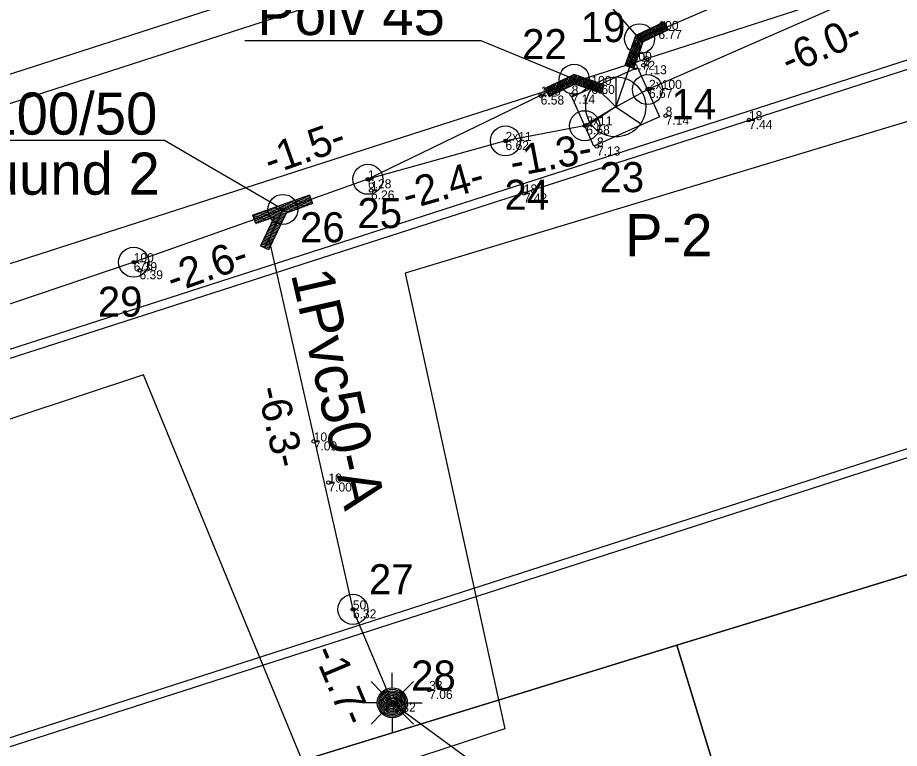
# Model space of a CAD drawing. Extents: x 546339 to 546593, y 6597108 to 6597251.
# Drawn here: x 546468.19 to 546482.86, y 6597179 to 6597191.16 of the extents above; entities that cross this region are included whole.
import ezdxf

# ---------------------------------------------------------------- set-up
doc = ezdxf.new("R2010")
doc.units = 0
for name, color, linetype in [('JOONSIDE', 7, 'Continuous'), ('KAEVUNR_SIKAEV', 7, 'Continuous'), ('KOORDPUNKT', 7, 'Continuous'), ('MOOTKORG-EH2000', 7, 'Continuous'), ('MOOTMPUNKT', 7, 'Continuous'), ('MOOTNR', 7, 'Continuous'), ('MOOTPIIR', 7, 'Continuous'), ('PIIR', 7, 'Continuous'), ('SIKAEV', 7, 'Continuous'), ('SITRASS', 7, 'Continuous'), ('TEE', 7, 'Continuous')]:
    doc.layers.add(name, color=color, linetype=linetype)

msp = doc.modelspace()

# ---------------------------------------------------------------- linework, layer by layer
at = {"layer": 'KOORDPUNKT'}
for centre, radius in [((546478.539, 6597190.81), 0.25), ((546478.539, 6597190.81), 0.025), ((546478.539, 6597190.81), 0.0221), ((546478.539, 6597190.81), 0.0191), ((546478.539, 6597190.81), 0.0161), ((546478.539, 6597190.81), 0.0132), ((546478.539, 6597190.81), 0.0102), ((546478.539, 6597190.81), 0.00726), ((546478.539, 6597190.81), 0.0043), ((546477.452, 6597190.136), 0.25), ((546477.452, 6597190.136), 0.025), ((546477.452, 6597190.136), 0.0221), ((546478.67, 6597189.965), 0.25), ((546477.452, 6597190.136), 0.0191), ((546477.452, 6597190.136), 0.0161), ((546477.452, 6597190.136), 0.0132), ((546477.452, 6597190.136), 0.0102), ((546477.452, 6597190.136), 0.00726), ((546477.452, 6597190.136), 0.0043), ((546478.67, 6597189.965), 0.025), ((546478.67, 6597189.965), 0.0221), ((546478.67, 6597189.965), 0.0191), ((546478.67, 6597189.965), 0.0161), ((546478.67, 6597189.965), 0.0132), ((546478.67, 6597189.965), 0.0102), ((546478.67, 6597189.965), 0.00726), ((546478.67, 6597189.965), 0.0043), ((546477.625, 6597189.363), 0.25), ((546476.307, 6597189.11), 0.25), ((546477.625, 6597189.363), 0.025), ((546477.625, 6597189.363), 0.0221), ((546477.625, 6597189.363), 0.0191), ((546477.625, 6597189.363), 0.0161), ((546477.625, 6597189.363), 0.0132), ((546477.625, 6597189.363), 0.0102), ((546477.625, 6597189.363), 0.00726), ((546477.625, 6597189.363), 0.0043), ((546476.307, 6597189.11), 0.025), ((546476.307, 6597189.11), 0.0221), ((546476.307, 6597189.11), 0.0191), ((546476.307, 6597189.11), 0.0161), ((546476.307, 6597189.11), 0.0132), ((546476.307, 6597189.11), 0.0102), ((546476.307, 6597189.11), 0.00726), ((546476.307, 6597189.11), 0.0043), ((546474.017, 6597188.471), 0.25), ((546474.017, 6597188.471), 0.025), ((546474.017, 6597188.471), 0.0221), ((546474.017, 6597188.471), 0.0191), ((546474.017, 6597188.471), 0.0161), ((546474.017, 6597188.471), 0.0132), ((546474.017, 6597188.471), 0.0102), ((546474.017, 6597188.471), 0.00726), ((546474.017, 6597188.471), 0.0043), ((546472.601, 6597187.97), 0.25), ((546472.601, 6597187.97), 0.025), ((546472.601, 6597187.97), 0.0221), ((546472.601, 6597187.97), 0.0191), ((546472.601, 6597187.97), 0.0161), ((546472.601, 6597187.97), 0.0132), ((546472.601, 6597187.97), 0.0102), ((546472.601, 6597187.97), 0.00726), ((546472.601, 6597187.97), 0.0043), ((546470.118, 6597187.092), 0.25), ((546470.118, 6597187.092), 0.025), ((546470.118, 6597187.092), 0.0221), ((546470.118, 6597187.092), 0.0191), ((546470.118, 6597187.092), 0.0161), ((546470.118, 6597187.092), 0.0132), ((546470.118, 6597187.092), 0.0102), ((546470.118, 6597187.092), 0.00726), ((546470.118, 6597187.092), 0.0043), ((546473.767, 6597181.315), 0.25), ((546473.767, 6597181.315), 0.025), ((546473.767, 6597181.315), 0.0221), ((546473.767, 6597181.315), 0.0191), ((546473.767, 6597181.315), 0.0161), ((546473.767, 6597181.315), 0.0132), ((546473.767, 6597181.315), 0.0102), ((546473.767, 6597181.315), 0.00726), ((546473.767, 6597181.315), 0.0043), ((546474.423, 6597179.76), 0.25), ((546474.423, 6597179.76), 0.025), ((546474.423, 6597179.76), 0.0221), ((546474.423, 6597179.76), 0.0191), ((546474.423, 6597179.76), 0.0161), ((546474.423, 6597179.76), 0.0132), ((546474.423, 6597179.76), 0.0102), ((546474.423, 6597179.76), 0.00726), ((546474.423, 6597179.76), 0.0043)]:
    msp.add_circle(centre, radius, dxfattribs=at)
at = {"layer": 'MOOTMPUNKT'}
for centre in [(546478.853, 6597190.956), (546478.407, 6597190.443), (546478.602, 6597190.369), (546477.737, 6597190.041), (546476.893, 6597189.865), (546477.409, 6597189.881), (546478.696, 6597189.976), (546478.973, 6597189.528), (546480.36, 6597189.456), (546477.653, 6597189.368), (546476.307, 6597189.11), (546477.829, 6597189.017), (546474.017, 6597188.471), (546474.068, 6597188.286), (546476.612, 6597188.235), (546470.118, 6597187.092), (546470.215, 6597186.957), (546473.115, 6597184.109), (546473.36, 6597183.425), (546473.767, 6597181.315), (546475.037, 6597179.974), (546474.423, 6597179.76)]:
    msp.add_circle(centre, 0.03, dxfattribs=at)
at = {"layer": 'MOOTPIIR'}
for points in [[(546431.038, 6597182.742), (546435.363, 6597179.169), (546476.861, 6597192.584), (546477.551, 6597196.157), (546480.466, 6597197.411), (546483.506, 6597194.527), (546510.21, 6597203.146)], [(546510.398, 6597198.602), (546490.433, 6597192.051), (546491.122, 6597184.372), (546487.988, 6597183.494), (546485.449, 6597190.17), (546474.636, 6597186.911), (546476.297, 6597179.326), (546473.131, 6597178.291), (546470.279, 6597185.218), (546447.869, 6597177.79), (546448.872, 6597171.02), (546446.584, 6597170.142), (546443.888, 6597176.348), (546374.62, 6597155.63)]]:
    msp.add_lwpolyline(points, dxfattribs=at)
at = {"layer": 'PIIR'}
for points in [[(546339.379, 6597150.424), (546339.82, 6597150.4), (546343.3, 6597148.09), (546350.66, 6597143.2), (546387.61, 6597151.42), (546402.5, 6597155.95), (546434.27, 6597166.43), (546452.55, 6597172.32), (546467.66, 6597177.18), (546479.16, 6597180.72), (546505.65, 6597188.82)], [(546512.531, 6597166.376), (546505.65, 6597188.82), (546479.16, 6597180.72), (546486.042, 6597158.239)], [(546486.042, 6597158.239), (546479.16, 6597180.72), (546467.66, 6597177.18), (546452.55, 6597172.32), (546459.381, 6597150.05)]]:
    msp.add_lwpolyline(points, dxfattribs=at)
at = {"layer": 'SIKAEV'}
for p, q in [((546478.142, 6597190.176), (546478.142, 6597189.676)), ((546478.142, 6597189.676), (546477.727, 6597189.401)), ((546478.142, 6597189.676), (546478.557, 6597189.401))]:
    msp.add_line(p, q, dxfattribs=at)
msp.add_lwpolyline([(546477.411, 6597189.842), (546478.506, 6597190.332), (546478.873, 6597189.51), (546477.778, 6597189.02)], close=True, dxfattribs=at)
msp.add_circle((546478.142, 6597189.676), 0.5, dxfattribs=at)
at = {"layer": 'SITRASS'}
for p, q in [((546478.957, 6597191.094), (546478.478, 6597190.864)), ((546478.904, 6597190.902), (546478.847, 6597191.042)), ((546478.926, 6597190.913), (546478.869, 6597191.052)), ((546478.949, 6597190.924), (546478.892, 6597191.063)), ((546478.971, 6597190.935), (546478.914, 6597191.074)), ((546478.994, 6597190.946), (546478.937, 6597191.085)), ((546479.022, 6597190.959), (546478.957, 6597191.094)), ((546479.016, 6597190.957), (546478.98, 6597191.046)), ((546478.989, 6597191.027), (546478.539, 6597190.81)), ((546478.61, 6597190.761), (546478.553, 6597190.9)), ((546478.633, 6597190.772), (546478.576, 6597190.911)), ((546478.655, 6597190.783), (546478.598, 6597190.922)), ((546479.022, 6597190.959), (546478.599, 6597190.756)), ((546478.678, 6597190.794), (546478.621, 6597190.933)), ((546478.7, 6597190.805), (546478.644, 6597190.944)), ((546478.723, 6597190.816), (546478.666, 6597190.955)), ((546478.746, 6597190.827), (546478.689, 6597190.966)), ((546478.768, 6597190.837), (546478.711, 6597190.976)), ((546478.791, 6597190.848), (546478.734, 6597190.987)), ((546478.813, 6597190.859), (546478.756, 6597190.998)), ((546478.836, 6597190.87), (546478.779, 6597191.009)), ((546478.858, 6597190.881), (546478.802, 6597191.02)), ((546478.881, 6597190.892), (546478.824, 6597191.031)), ((546478.302, 6597190.363), (546478.478, 6597190.864)), ((546478.373, 6597190.338), (546478.539, 6597190.81)), ((546478.444, 6597190.314), (546478.599, 6597190.756)), ((546478.53, 6597190.56), (546478.445, 6597190.77)), ((546478.543, 6597190.596), (546478.457, 6597190.805)), ((546478.555, 6597190.632), (546478.47, 6597190.841)), ((546478.568, 6597190.667), (546478.486, 6597190.868)), ((546478.58, 6597190.703), (546478.508, 6597190.879)), ((546478.593, 6597190.738), (546478.531, 6597190.89)), ((546478.481, 6597190.418), (546478.395, 6597190.627)), ((546478.493, 6597190.454), (546478.407, 6597190.663)), ((546478.506, 6597190.489), (546478.42, 6597190.698)), ((546478.518, 6597190.525), (546478.432, 6597190.734)), ((546478.411, 6597190.325), (546478.345, 6597190.485)), ((546478.442, 6597190.314), (546478.358, 6597190.521)), ((546478.456, 6597190.347), (546478.37, 6597190.556)), ((546478.468, 6597190.383), (546478.382, 6597190.592)), ((546478.444, 6597190.314), (546478.302, 6597190.363)), ((546478.316, 6597190.358), (546478.308, 6597190.379)), ((546478.348, 6597190.347), (546478.32, 6597190.414)), ((546478.379, 6597190.336), (546478.333, 6597190.45)), ((546476.969, 6597189.986), (546477.447, 6597190.217)), ((546477.27, 6597189.965), (546477.357, 6597190.174)), ((546477.304, 6597189.981), (546477.39, 6597190.19)), ((546477.338, 6597189.998), (546477.424, 6597190.206)), ((546477.372, 6597190.014), (546477.455, 6597190.215)), ((546477.406, 6597190.031), (546477.478, 6597190.206)), ((546477.439, 6597190.047), (546477.502, 6597190.198)), ((546477.949, 6597190.043), (546477.447, 6597190.217)), ((546477.468, 6597190.051), (546477.526, 6597190.19)), ((546477.492, 6597190.043), (546477.549, 6597190.182)), ((546477.516, 6597190.035), (546477.573, 6597190.174)), ((546477.539, 6597190.027), (546477.597, 6597190.165)), ((546477.002, 6597189.918), (546477.452, 6597190.136)), ((546477.005, 6597189.912), (546477.052, 6597190.026)), ((546477.019, 6597189.882), (546477.086, 6597190.042)), ((546477.034, 6597189.852), (546477.119, 6597190.059)), ((546477.035, 6597189.851), (546477.456, 6597190.055)), ((546477.067, 6597189.866), (546477.153, 6597190.075)), ((546477.101, 6597189.883), (546477.187, 6597190.091)), ((546477.134, 6597189.899), (546477.221, 6597190.108)), ((546477.168, 6597189.916), (546477.255, 6597190.124)), ((546477.202, 6597189.932), (546477.289, 6597190.141)), ((546477.236, 6597189.948), (546477.323, 6597190.157)), ((546477.924, 6597189.972), (546477.452, 6597190.136)), ((546477.9, 6597189.902), (546477.456, 6597190.055)), ((546477.563, 6597190.018), (546477.62, 6597190.157)), ((546477.587, 6597190.01), (546477.644, 6597190.149)), ((546477.61, 6597190.002), (546477.668, 6597190.141)), ((546477.634, 6597189.994), (546477.691, 6597190.133)), ((546477.657, 6597189.986), (546477.715, 6597190.124)), ((546477.681, 6597189.977), (546477.739, 6597190.116)), ((546477.705, 6597189.969), (546477.762, 6597190.108)), ((546477.728, 6597189.961), (546477.786, 6597190.1)), ((546477.752, 6597189.953), (546477.81, 6597190.092)), ((546477.776, 6597189.945), (546477.833, 6597190.083)), ((546477.799, 6597189.936), (546477.857, 6597190.075)), ((546477.823, 6597189.928), (546477.881, 6597190.067)), ((546477.847, 6597189.92), (546477.904, 6597190.059)), ((546477.87, 6597189.912), (546477.928, 6597190.051)), ((546477.9, 6597189.902), (546477.949, 6597190.043)), ((546477.035, 6597189.851), (546476.969, 6597189.986)), ((546476.975, 6597189.973), (546476.984, 6597189.993)), ((546476.99, 6597189.943), (546477.018, 6597190.009)), ((546477.894, 6597189.904), (546477.931, 6597189.993)), ((546473.047, 6597188.208), (546472.104, 6597187.874)), ((546473.072, 6597188.137), (546472.129, 6597187.803)), ((546472.753, 6597188.103), (546472.997, 6597188.031)), ((546472.793, 6597188.118), (546473.036, 6597188.045)), ((546472.833, 6597188.132), (546473.076, 6597188.059)), ((546472.873, 6597188.146), (546473.092, 6597188.08)), ((546472.913, 6597188.16), (546473.082, 6597188.109)), ((546472.953, 6597188.174), (546473.071, 6597188.139)), ((546472.993, 6597188.188), (546473.061, 6597188.168)), ((546473.033, 6597188.202), (546473.051, 6597188.197)), ((546473.047, 6597188.208), (546473.097, 6597188.066)), ((546472.601, 6597187.97), (546472.296, 6597187.332)), ((546472.353, 6597187.962), (546472.639, 6597187.876)), ((546472.393, 6597187.976), (546472.65, 6597187.899)), ((546472.433, 6597187.99), (546472.677, 6597187.917)), ((546472.473, 6597188.004), (546472.717, 6597187.932)), ((546472.513, 6597188.019), (546472.757, 6597187.946)), ((546472.553, 6597188.033), (546472.797, 6597187.96)), ((546472.593, 6597188.047), (546472.837, 6597187.974)), ((546472.633, 6597188.061), (546472.877, 6597187.988)), ((546473.097, 6597188.066), (546472.655, 6597187.91)), ((546472.673, 6597188.075), (546472.917, 6597188.002)), ((546472.713, 6597188.089), (546472.957, 6597188.016)), ((546472.154, 6597187.733), (546472.104, 6597187.874)), ((546472.112, 6597187.851), (546472.317, 6597187.79)), ((546472.113, 6597187.877), (546472.357, 6597187.804)), ((546472.123, 6597187.822), (546472.277, 6597187.776)), ((546472.153, 6597187.891), (546472.397, 6597187.818)), ((546472.455, 6597187.839), (546472.154, 6597187.733)), ((546472.193, 6597187.905), (546472.437, 6597187.833)), ((546472.455, 6597187.839), (546472.228, 6597187.364)), ((546472.233, 6597187.92), (546472.606, 6597187.808)), ((546472.273, 6597187.934), (546472.617, 6597187.831)), ((546472.313, 6597187.948), (546472.628, 6597187.854)), ((546472.655, 6597187.91), (546472.364, 6597187.3)), ((546472.45, 6597187.829), (546472.596, 6597187.785)), ((546472.133, 6597187.793), (546472.237, 6597187.762)), ((546472.143, 6597187.764), (546472.197, 6597187.748)), ((546472.154, 6597187.735), (546472.157, 6597187.734)), ((546472.374, 6597187.669), (546472.519, 6597187.625)), ((546472.385, 6597187.692), (546472.53, 6597187.648)), ((546472.396, 6597187.714), (546472.541, 6597187.671)), ((546472.406, 6597187.737), (546472.552, 6597187.694)), ((546472.417, 6597187.76), (546472.563, 6597187.717)), ((546472.428, 6597187.783), (546472.574, 6597187.739)), ((546472.439, 6597187.806), (546472.585, 6597187.762)), ((546472.308, 6597187.532), (546472.454, 6597187.488)), ((546472.319, 6597187.555), (546472.465, 6597187.511)), ((546472.33, 6597187.577), (546472.476, 6597187.534)), ((546472.341, 6597187.6), (546472.486, 6597187.557)), ((546472.352, 6597187.623), (546472.497, 6597187.58)), ((546472.363, 6597187.646), (546472.508, 6597187.602)), ((546472.232, 6597187.372), (546472.377, 6597187.328)), ((546472.243, 6597187.395), (546472.388, 6597187.351)), ((546472.254, 6597187.418), (546472.399, 6597187.374)), ((546472.265, 6597187.44), (546472.41, 6597187.397)), ((546472.276, 6597187.463), (546472.421, 6597187.42)), ((546472.287, 6597187.486), (546472.432, 6597187.443)), ((546472.297, 6597187.509), (546472.443, 6597187.465)), ((546472.364, 6597187.3), (546472.228, 6597187.364)), ((546472.326, 6597187.318), (546472.367, 6597187.306)), ((546474.423, 6597180.01), (546474.423, 6597180.26)), ((546474.246, 6597179.937), (546474.069, 6597180.114)), ((546474.6, 6597179.937), (546474.777, 6597180.114)), ((546474.173, 6597179.76), (546473.923, 6597179.76)), ((546474.673, 6597179.76), (546474.923, 6597179.76)), ((546474.246, 6597179.583), (546474.069, 6597179.406)), ((546474.423, 6597179.51), (546474.423, 6597179.26)), ((546474.6, 6597179.583), (546474.777, 6597179.406))]:
    msp.add_line(p, q, dxfattribs=at)
for points in [[(546478.539, 6597190.81), (546476.485, 6597193.15), (546472.55, 6597193.15)], [(546478.142, 6597189.676), (546478.67, 6597189.965), (546484.189, 6597192.382)], [(546480.094, 6597191.481), (546478.539, 6597190.81), (546478.346, 6597190.26), (546478.142, 6597189.676)], [(546477.452, 6597190.136), (546475.905, 6597190.773), (546471.971, 6597190.773)], [(546478.142, 6597189.676), (546477.799, 6597190.016), (546477.452, 6597190.136), (546474.017, 6597188.471)], [(546478.142, 6597189.676), (546477.625, 6597189.363), (546476.307, 6597189.11), (546474.017, 6597188.471)], [(546472.601, 6597187.97), (546470.63, 6597189.117), (546462.729, 6597189.117)], [(546474.017, 6597188.471), (546472.601, 6597187.97)], [(546472.601, 6597187.97), (546470.118, 6597187.092), (546462.018, 6597184.359), (546455.281, 6597182.437), (546447.986, 6597180.224), (546445.217, 6597179.513)], [(546472.601, 6597187.97), (546472.366, 6597187.478), (546473.767, 6597181.315), (546474.423, 6597179.76)], [(546474.423, 6597179.76), (546476.959, 6597177.904), (546485.856, 6597177.904)]]:
    msp.add_lwpolyline(points, dxfattribs=at)
for radius in [0.25, 0.225, 0.2, 0.175, 0.15, 0.125, 0.1, 0.075, 0.05, 0.025]:
    msp.add_circle((546474.423, 6597179.76), radius, dxfattribs=at)
at = {"layer": 'TEE'}
for p, q in [((546518.272, 6597195.197), (546396.577, 6597156.011)), ((546439.027, 6597176.299), (546484.965, 6597191.091)), ((546484.87, 6597190.902), (546439.237, 6597176.208))]:
    msp.add_line(p, q, dxfattribs=at)
for points in [[(546514.456, 6597205.157), (546396.804, 6597167.285), (546396.804, 6597167.285)], [(546515.375, 6597202.301), (546397.724, 6597164.429), (546397.724, 6597164.429)], [(546396.531, 6597156.154), (546518.226, 6597195.34), (546518.226, 6597195.34)]]:
    msp.add_lwpolyline(points, dxfattribs=at)

# ---------------------------------------------------------------- texts
at = {"layer": 'JOONSIDE'}
for s, rotation, p in [('-6.0-', 23.654, (546481.024, 6597190.202)), ('-1.5-', 19.4777, (546472.391, 6597188.533)), ('-1.3-', 10.8508, (546476.43, 6597188.507)), ('-2.4-', 15.5912, (546474.667, 6597187.956)), ('-2.6-', 19.4777, (546470.768, 6597186.57)), ('-6.3-', 282.8112, (546472.172, 6597184.979)), ('-1.7-', 292.8732, (546473.097, 6597180.606))]:
    msp.add_text(s, height=0.5, rotation=rotation, dxfattribs=at).set_placement(p)
at = {"layer": 'KAEVUNR_SIKAEV'}
msp.add_text('P-2', height=0.7, dxfattribs=at).set_placement((546478.297, 6597187.191))
at = {"layer": 'KOORDPUNKT'}
for s, p in [('19', (546477.56, 6597190.754)), ('22', (546476.584, 6597190.471)), ('14', (546479.068, 6597189.471)), ('23', (546477.872, 6597188.257)), ('24', (546476.291, 6597187.964)), ('25', (546473.842, 6597187.659)), ('26', (546472.887, 6597187.423)), ('29', (546469.521, 6597186.185)), ('27', (546474.033, 6597181.566)), ('28', (546474.736, 6597179.964))]:
    msp.add_text(s, height=0.5, dxfattribs=at).set_placement(p)
at = {"layer": 'MOOTKORG-EH2000'}
for s, p in [('6.77', (546478.853, 6597190.806)), ('6.72', (546478.407, 6597190.293)), ('7.13', (546478.602, 6597190.219)), ('6.60', (546477.737, 6597189.891)), ('6.58', (546476.893, 6597189.715)), ('7.14', (546477.409, 6597189.731)), ('6.67', (546478.696, 6597189.826)), ('7.14', (546478.973, 6597189.378)), ('7.44', (546480.36, 6597189.306)), ('6.58', (546477.653, 6597189.218)), ('6.62', (546476.307, 6597188.96)), ('7.13', (546477.829, 6597188.867)), ('6.28', (546474.017, 6597188.321)), ('6.26', (546474.068, 6597188.136)), ('7.42', (546476.612, 6597188.085)), ('6.39', (546470.118, 6597186.942)), ('6.39', (546470.215, 6597186.807)), ('7.09', (546473.115, 6597183.959)), ('7.00', (546473.36, 6597183.275)), ('6.32', (546473.767, 6597181.165)), ('7.06', (546475.037, 6597179.824)), ('6.32', (546474.423, 6597179.61))]:
    msp.add_text(s, height=0.15, dxfattribs=at).set_placement(p)
at = {"layer": 'MOOTNR'}
for s, p in [('100', (546478.853, 6597190.956)), ('100', (546478.407, 6597190.443)), ('8', (546478.602, 6597190.369)), ('100', (546477.737, 6597190.041)), ('100', (546476.893, 6597189.865)), ('8', (546477.409, 6597189.881)), ('2x100', (546478.696, 6597189.976)), ('8', (546478.973, 6597189.528)), ('18', (546480.36, 6597189.456)), ('2x11', (546477.653, 6597189.368)), ('2x11', (546476.307, 6597189.11)), ('8', (546477.829, 6597189.017)), ('1', (546474.017, 6597188.471)), ('1', (546474.068, 6597188.286)), ('18', (546476.612, 6597188.235)), ('100', (546470.118, 6597187.092)), ('75', (546470.215, 6597186.957)), ('10', (546473.115, 6597184.109)), ('10', (546473.36, 6597183.425)), ('50', (546473.767, 6597181.315)), ('33', (546475.037, 6597179.974)), ('50', (546474.423, 6597179.76))]:
    msp.add_text(s, height=0.15, dxfattribs=at).set_placement(p)
at = {"layer": 'SITRASS'}
for s, p in [('Põlv 45°', (546472.176, 6597190.871)), ('Sadulharu 100/50', (546463.121, 6597189.215)), ('P2 suund 2', (546465.816, 6597188.215))]:
    msp.add_text(s, height=0.7, dxfattribs=at).set_placement(p)
msp.add_text('1Pvc50-A', height=0.7, rotation=282.8112, dxfattribs=at).set_placement((546472.734, 6597186.894))

doc.saveas('drawing.dxf')
